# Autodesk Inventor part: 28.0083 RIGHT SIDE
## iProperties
Created: 2006-12
Part Number: 28.0083 RIGHT SIDE
Document SubType Name: Modeling
Designer: Andy Moles
Material: Aluminum-6061
Density: 2.71 g/cm^3
Author: Andy Moles
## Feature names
1. Extrusion1
2. Extrusion2
3. Extrusion3
4. Extrusion4
5. Extrusion5
6. Hole1
7. Hole2
8. Hole3
9. Extrusion6
10. Chamfer1
